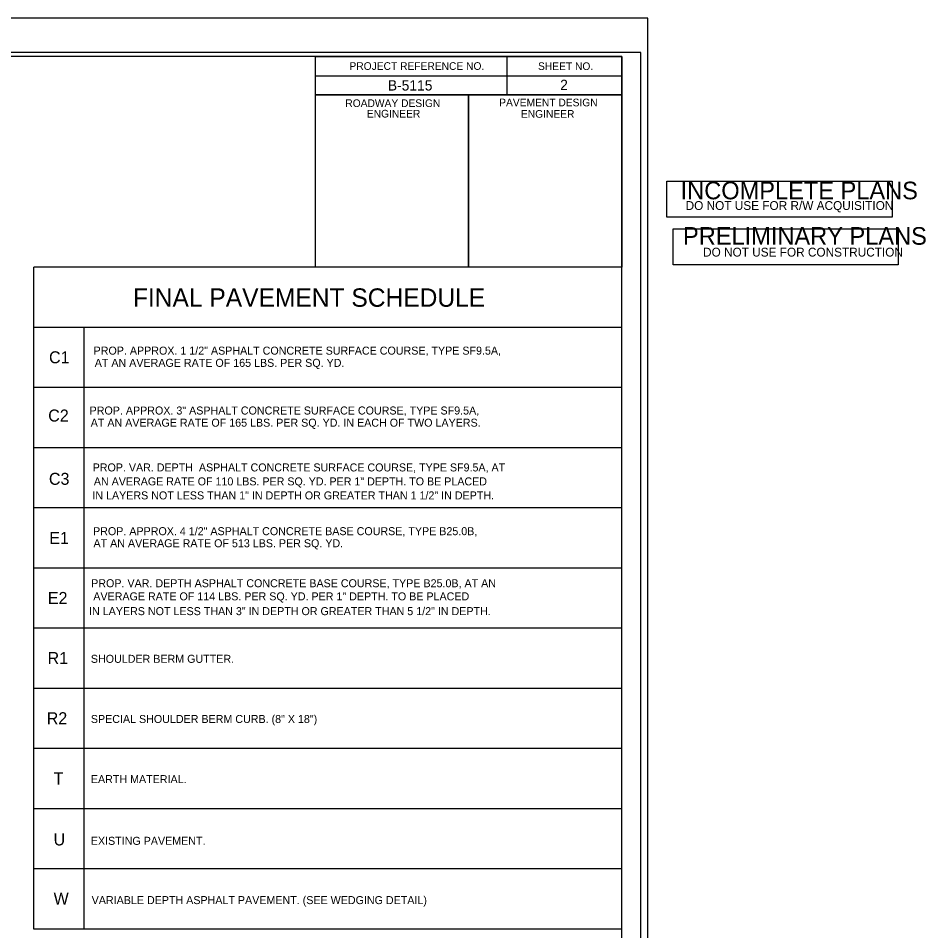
# Model space of a CAD drawing. Extents: x 573687 to 575553, y -54556 to -52223.
# Drawn here: x 574960 to 575553, y -52818 to -52223 of the extents above; entities that cross this region are included whole.
import ezdxf

# ---------------------------------------------------------------- set-up
doc = ezdxf.new("R2010")
doc.units = 0
for name, color, linetype in [('Default', 7, 'Continuous'), ('Sheet Cutting Line CELL', 7, 'Continuous'), ('Sheet Data Field CELL', 7, 'Continuous'), ('Sheet Plot Border Inside CELL', 7, 'Continuous'), ('Sheet Plot Border Outside CELL', 7, 'Continuous'), ('Sheet Sticker Incomplete CELL', 7, 'Continuous'), ('Sheet Sticker Preliminary CELL', 7, 'Continuous'), ('Sheet Typical CELL', 7, 'Continuous'), ('Typical Text Label CELL', 7, 'Continuous')]:
    doc.layers.add(name, color=color, linetype=linetype)

msp = doc.modelspace()

# ---------------------------------------------------------------- linework, layer by layer
at = {"layer": 'Default'}
for p, q in [((574970.43, -52424.5), (574970.43, -52385.22)), ((575354.43, -52385.22), (574970.43, -52385.22)), ((575354.43, -52424.5), (575354.43, -52385.22)), ((574970.43, -52463.78), (574970.43, -52424.5)), ((575354.43, -52424.5), (574970.43, -52424.5)), ((575003.38, -52463.78), (575003.38, -52424.5)), ((575354.43, -52463.78), (575354.43, -52424.5)), ((575354.43, -52463.78), (574970.43, -52463.78)), ((574970.43, -52503.06), (574970.43, -52463.78)), ((575003.38, -52503.06), (575003.38, -52463.78)), ((575354.43, -52503.06), (575354.43, -52463.78)), ((574970.43, -52542.34), (574970.43, -52503.06)), ((575009.7, -52503.06), (574970.43, -52503.06)), ((575003.38, -52542.34), (575003.38, -52503.06)), ((575354.43, -52503.06), (575009.7, -52503.06)), ((575354.43, -52542.34), (575354.43, -52503.06)), ((574970.43, -52581.62), (574970.43, -52542.34)), ((575009.7, -52542.34), (574970.43, -52542.34)), ((575003.38, -52581.62), (575003.38, -52542.34)), ((575354.43, -52542.34), (575009.7, -52542.34)), ((575354.43, -52581.62), (575354.43, -52542.34)), ((574970.43, -52620.9), (574970.43, -52581.62)), ((575009.7, -52581.62), (574970.43, -52581.62)), ((575003.38, -52620.9), (575003.38, -52581.62)), ((575354.43, -52581.62), (575009.7, -52581.62)), ((575354.43, -52620.9), (575354.43, -52581.62)), ((574970.43, -52660.18), (574970.43, -52620.9)), ((575009.7, -52620.9), (574970.43, -52620.9)), ((575003.38, -52660.18), (575003.38, -52620.9)), ((575354.43, -52620.9), (575009.7, -52620.9)), ((575354.43, -52660.18), (575354.43, -52620.9)), ((575009.7, -52660.18), (574970.43, -52660.18)), ((574970.43, -52699.46), (574970.43, -52660.18)), ((575009.7, -52660.18), (574970.43, -52660.18)), ((575003.38, -52699.46), (575003.38, -52660.18)), ((575354.43, -52660.18), (575009.7, -52660.18)), ((575354.43, -52660.18), (575009.7, -52660.18)), ((575354.43, -52699.46), (575354.43, -52660.18)), ((574970.43, -52738.74), (574970.43, -52699.46)), ((575009.7, -52699.46), (574970.43, -52699.46)), ((575009.7, -52699.46), (574970.43, -52699.46)), ((575003.38, -52738.74), (575003.38, -52699.46)), ((575354.43, -52699.46), (575009.7, -52699.46)), ((575354.43, -52699.46), (575009.7, -52699.46)), ((575354.43, -52738.74), (575354.43, -52699.46)), ((574970.43, -52778.02), (574970.43, -52738.74)), ((575009.7, -52738.74), (574970.43, -52738.74)), ((575003.38, -52778.02), (575003.38, -52738.74)), ((575354.43, -52738.74), (575009.7, -52738.74)), ((575354.43, -52778.02), (575354.43, -52738.74)), ((574970.43, -52817.3), (574970.43, -52778.02)), ((575009.7, -52778.02), (574970.43, -52778.02)), ((575003.38, -52817.3), (575003.38, -52778.02)), ((575354.43, -52778.02), (575009.7, -52778.02)), ((575354.43, -52817.3), (575354.43, -52778.02)), ((575009.7, -52817.3), (574970.43, -52817.3)), ((575354.43, -52817.3), (575009.7, -52817.3))]:
    msp.add_line(p, q, dxfattribs=at)
at = {"layer": 'Sheet Cutting Line CELL'}
msp.add_line((575371.43, -52222.67), (573687.43, -52222.67), dxfattribs=at)
at = {"layer": 'Sheet Plot Border Inside CELL'}
msp.add_lwpolyline([(575366.93, -52245.12), (573700.43, -52245.12), (573700.43, -53300.22), (575366.93, -53300.22)], close=True, dxfattribs=at)
at = {"layer": 'Sheet Plot Border Outside CELL'}
msp.add_lwpolyline([(575371.43, -52222.67), (573687.43, -52222.67), (573687.43, -53322.67), (575371.43, -53322.67)], close=True, dxfattribs=at)
at = {"layer": 'Sheet Sticker Incomplete CELL'}
msp.add_lwpolyline([(575383.92, -52352.57), (575383.92, -52329.07), (575530.92, -52329.07), (575530.92, -52352.57)], close=True, dxfattribs=at)
at = {"layer": 'Sheet Sticker Preliminary CELL'}
msp.add_lwpolyline([(575387.91, -52383.7), (575387.91, -52360.2), (575534.91, -52360.2), (575534.91, -52383.7)], close=True, dxfattribs=at)
at = {"layer": 'Sheet Typical CELL'}
for p, q in [((575279.43, -52247.72), (575279.43, -52272.72)), ((575154.38, -52260.22), (575354.43, -52260.22)), ((575254.43, -52272.72), (575254.43, -52385.17))]:
    msp.add_line(p, q, dxfattribs=at)
for points in [[(575354.43, -52247.67), (573854.43, -52247.67), (573854.43, -53297.67), (575354.43, -53297.67)], [(575154.38, -52247.67), (575354.43, -52247.67), (575354.43, -52272.72), (575154.38, -52272.72)], [(575154.38, -52272.72), (575254.43, -52272.72), (575254.43, -52385.22), (575154.38, -52385.22)], [(575254.43, -52272.72), (575354.43, -52272.72), (575354.43, -52385.22), (575254.43, -52385.22)]]:
    msp.add_lwpolyline(points, close=True, dxfattribs=at)

# ---------------------------------------------------------------- texts
at = {"layer": 'Default'}
for s, height, p in [('C1', 7.84, (574980.41, -52447.94)), ('PROP. APPROX. 1 1/2" ASPHALT CONCRETE SURFACE COURSE, TYPE SF9.5A, ', 5.224, (575009.5, -52442.28)), ('AT AN AVERAGE RATE OF 165 LBS. PER SQ. YD.', 5.224, (575010.24, -52450.25)), ('C2', 7.84, (574979.85, -52485.96)), ('PROP. APPROX. 3" ASPHALT CONCRETE SURFACE COURSE, TYPE SF9.5A, ', 5.224, (575006.88, -52481.37)), ('AT AN AVERAGE RATE OF 165 LBS. PER SQ. YD. IN EACH OF TWO LAYERS.', 5.224, (575007.62, -52489.33)), ('IN LAYERS NOT LESS THAN 1" IN DEPTH OR GREATER THAN 1 1/2" IN DEPTH.', 5.224, (575008.69, -52536.8)), ('PROP. APPROX. 4 1/2" ASPHALT CONCRETE BASE COURSE, TYPE B25.0B,', 5.224, (575009.15, -52560.15)), ('AT AN AVERAGE RATE OF 513 LBS. PER SQ. YD. ', 5.224, (575009.41, -52568.04)), ('E2', 7.84, (574979.62, -52605.07))]:
    msp.add_text(s, height=height, rotation=360, dxfattribs=at).set_placement(p)
for s, height, p in [('PROP. VAR. DEPTH  ASPHALT CONCRETE SURFACE COURSE, TYPE SF9.5A, AT', 5.2158, (575008.9, -52518.53)), ('C3', 7.828, (574980.33, -52527.28)), ('AN AVERAGE RATE OF 110 LBS. PER SQ. YD. PER 1" DEPTH. TO BE PLACED', 5.2158, (575009.66, -52527.65)), ('E1', 7.828, (574980.56, -52565.85)), ('PROP. VAR. DEPTH ASPHALT CONCRETE BASE COURSE, TYPE B25.0B, AT AN', 5.224, (575007.92, -52594.15)), ('AVERAGE RATE OF 114 LBS. PER SQ. YD. PER 1" DEPTH. TO BE PLACED', 5.224, (575009.3, -52602.71)), ('IN LAYERS NOT LESS THAN 3" IN DEPTH OR GREATER THAN 5 1/2" IN DEPTH.', 5.224, (575006.54, -52612.36)), ('R1', 7.84, (574979.45, -52644.29)), ('SHOULDER BERM GUTTER.', 5.224, (575007.71, -52643.49)), ('R2', 7.84, (574978.89, -52683.57)), ('SPECIAL SHOULDER BERM CURB. (8" X 18")', 5.224, (575007.71, -52682.77)), ('T', 7.84, (574983.37, -52722.93)), ('EARTH MATERIAL.', 5.224, (575007.71, -52722.05)), ('U', 7.84, (574983.37, -52762.72)), ('EXISTING PAVEMENT.', 5.224, (575007.67, -52762.31)), ('W', 7.84, (574983.37, -52801.29)), ('VARIABLE DEPTH ASPHALT PAVEMENT. (SEE WEDGING DETAIL)', 5.224, (575008.24, -52801.01))]:
    msp.add_text(s, height=height, dxfattribs=at).set_placement(p)
at = {"layer": 'Sheet Data Field CELL'}
for s, p in [('B-5115', (575201.67, -52269.87)), ('2', (575314.19, -52269.57))]:
    msp.add_text(s, height=6.75, dxfattribs=at).set_placement(p)
at = {"layer": 'Sheet Sticker Incomplete CELL'}
for s, height, p in [('INCOMPLETE PLANS', 11.52, (575392.87, -52340.87)), ('DO NOT USE FOR R/W ACQUISITION', 5.76, (575396.12, -52347.82))]:
    msp.add_text(s, height=height, dxfattribs=at).set_placement(p)
at = {"layer": 'Sheet Sticker Preliminary CELL'}
for s, height, p in [('PRELIMINARY PLANS', 11.52, (575394.41, -52370.55)), ('DO NOT USE FOR CONSTRUCTION', 5.76, (575407.51, -52378.25)), ('DO NOT USE FOR CONSTRUCTION', 5.76, (575407.51, -52378.25))]:
    msp.add_text(s, height=height, dxfattribs=at).set_placement(p)
at = {"layer": 'Sheet Typical CELL'}
for s, height, p in [('PROJECT REFERENCE NO.', 5.0001, (575176.58, -52256.37)), ('SHEET NO.', 5, (575299.73, -52256.47)), ('ROADWAY DESIGN', 5.0001, (575173.88, -52280.62)), ('PAVEMENT DESIGN', 5.0001, (575274.38, -52280.17)), ('ENGINEER', 5, (575187.93, -52287.47)), ('ENGINEER', 5, (575288.58, -52287.62))]:
    msp.add_text(s, height=height, dxfattribs=at).set_placement(p)
at = {"layer": 'Typical Text Label CELL'}
msp.add_text('FINAL PAVEMENT SCHEDULE', height=12, dxfattribs=at).set_placement((575035.16, -52411.03))

doc.saveas('drawing.dxf')
